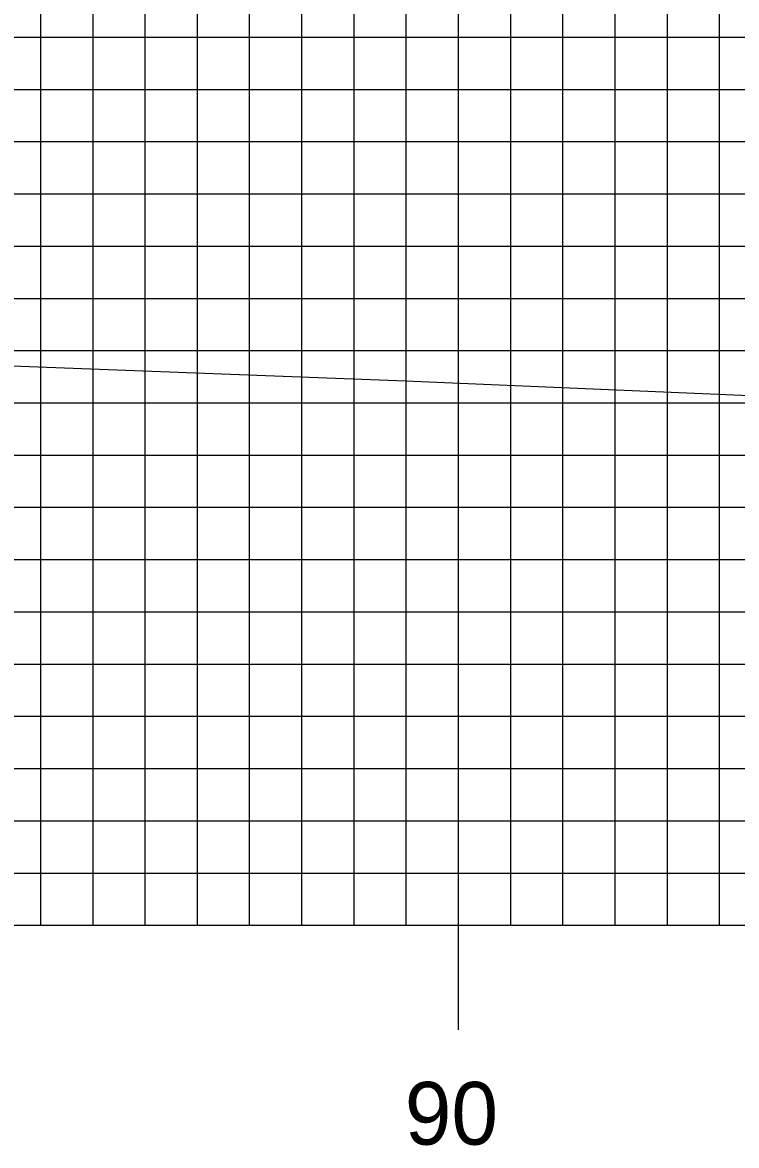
# Model space of a CAD drawing. Extents: x 1781467 to 1781810, y 442591 to 442811.
# Drawn here: x 1781534.06 to 1781547.73, y 442659.45 to 442680.95 of the extents above; entities that cross this region are included whole.
import ezdxf

# ---------------------------------------------------------------- set-up
doc = ezdxf.new("R2010")
doc.units = 0
for name, color, linetype in [('H_V ANNOTATION', 7, 'Continuous'), ('MAJOR', 7, 'Continuous'), ('MINOR', 7, 'Continuous'), ('S_Roadway_Centerline', 7, 'Continuous')]:
    doc.layers.add(name, color=color, linetype=linetype)

msp = doc.modelspace()

# ---------------------------------------------------------------- linework, layer by layer
at = {"layer": 'MAJOR'}
for p, q in [((1781542.408, 442663.665), (1781542.408, 442698.665)), ((1781492.408, 442678.665), (1781772.408, 442678.665)), ((1781492.408, 442673.665), (1781772.408, 442673.665)), ((1781492.408, 442668.665), (1781772.408, 442668.665)), ((1781492.408, 442663.665), (1781772.408, 442663.665)), ((1781492.408, 442663.665), (1781772.408, 442663.665)), ((1781542.408, 442661.661), (1781542.408, 442663.665))]:
    msp.add_line(p, q, dxfattribs=at)
at = {"layer": 'MINOR'}
for p, q in [((1781534.408, 442663.665), (1781534.408, 442698.665)), ((1781535.408, 442663.665), (1781535.408, 442698.665)), ((1781536.408, 442663.665), (1781536.408, 442698.665)), ((1781537.408, 442663.665), (1781537.408, 442698.665)), ((1781538.408, 442663.665), (1781538.408, 442698.665)), ((1781539.408, 442663.665), (1781539.408, 442698.665)), ((1781540.408, 442663.665), (1781540.408, 442698.665)), ((1781541.408, 442663.665), (1781541.408, 442698.665)), ((1781543.408, 442663.665), (1781543.408, 442698.665)), ((1781544.408, 442663.665), (1781544.408, 442698.665)), ((1781545.408, 442663.665), (1781545.408, 442698.665)), ((1781546.408, 442663.665), (1781546.408, 442698.665)), ((1781547.408, 442663.665), (1781547.408, 442698.665)), ((1781492.408, 442680.665), (1781772.408, 442680.665)), ((1781492.408, 442679.665), (1781772.408, 442679.665)), ((1781492.408, 442677.665), (1781772.408, 442677.665)), ((1781492.408, 442676.665), (1781772.408, 442676.665)), ((1781492.408, 442675.665), (1781772.408, 442675.665)), ((1781492.408, 442674.665), (1781772.408, 442674.665)), ((1781492.408, 442672.665), (1781772.408, 442672.665)), ((1781492.408, 442671.665), (1781772.408, 442671.665)), ((1781492.408, 442670.665), (1781772.408, 442670.665)), ((1781492.408, 442669.665), (1781772.408, 442669.665)), ((1781492.408, 442667.665), (1781772.408, 442667.665)), ((1781492.408, 442666.665), (1781772.408, 442666.665)), ((1781492.408, 442665.665), (1781772.408, 442665.665)), ((1781492.408, 442664.665), (1781772.408, 442664.665))]:
    msp.add_line(p, q, dxfattribs=at)
at = {"layer": 'S_Roadway_Centerline'}
msp.add_lwpolyline([(1781492.408, 442676.385), (1781508.31, 442675.463), (1781512.714, 442675.229), (1781517.267, 442674.997), (1781532.006, 442674.445), (1781541.391, 442674.084), (1781554.263, 442673.537), (1781559.209, 442673.54), (1781577.11, 442673.042), (1781588.859, 442672.808), (1781593.637, 442672.549), (1781598.923, 442672.598), (1781605.769, 442672.682)], dxfattribs=at)

# ---------------------------------------------------------------- texts
at = {"layer": 'H_V ANNOTATION'}
msp.add_text('90', height=1.2, dxfattribs=at).set_placement((1781541.38, 442659.465))

doc.saveas('drawing.dxf')
